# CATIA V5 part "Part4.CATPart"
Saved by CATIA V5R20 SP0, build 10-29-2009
Part number: Part4
Bounding box of the stored display mesh (mm): x -50 to 50, y -35 to 35, z 0 to 75
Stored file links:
  C:\Users\Lenovo\Desktop\存钱\Part4.CATPart
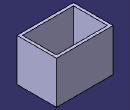
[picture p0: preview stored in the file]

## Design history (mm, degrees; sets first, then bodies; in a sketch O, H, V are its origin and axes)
Body1 (main body)
  Sketch1 on xy-plane, origin (0, 0, 0), H (1, 0, 0), V (0, 1, 0)
    line L1 (50, 35) -> (50, -35)
    line L2 (50, -35) -> (-50, -35)
    line L3 (-50, -35) -> (-50, 35)
    line L4 (-50, 35) -> (50, 35)
    length L4 = 100
    length L1 = 70
    vertical: L1 V, L3 V
    horizontal: L2 H, L4 H
    equidistance: L1 L3 O, L2 L4 O
  Pad1: profile Sketch1, direction (0, 0, 1), length 5
  Sketch2 on end face of Pad1, origin (0, 0, 5), H (1, 0, 0), V (0, 1, 0)
    line L1 (-50, 35) -> (-45, 35)
    line L2 (-45, 35) -> (-45, -35)
    line L3 (-45, -35) -> (-50, -35)
    line L4 (-50, -35) -> (-50, 35)
    reference projected line E1 (50, 35) -> (-50, 35) from edge [face of Pad1 from Sketch1.L4 | end face of Pad1]
    reference projected line E2 (-50, -35) -> (50, -35) from edge [face of Pad1 from Sketch1.L2 | end face of Pad1]
    reference projected line E3 (-50, 35) -> (-50, -35) from edge [face of Pad1 from Sketch1.L3 | end face of Pad1]
    length L1 = 5
    horizontal: L1 H, L3 H
    vertical: L2 V, L4 V
    coincidence: L1 E1, L3 E2, L4 E3
  Pad2: profile Sketch2, direction (0, 0, 1), length 70
  Mirror1: of the body so far, about yz-plane
  Sketch3 on face of Pad2, origin (0, -35, 0), H (1, 0, 0), V (0, 0, 1)
    line L1 (-50, 75) -> (50, 75)
    line L2 (50, 75) -> (50, 0)
    line L3 (50, 0) -> (-50, 0)
    line L4 (-50, 0) -> (-50, 75)
    reference projected line E1 (-50, 0) -> (50, 0) from edge [face of Mirror1 | face of Pad2]
    reference projected line E2 (50, 0) -> (50, 75) from edge [face of Mirror1 | face of Pad2]
    reference projected line E3 (-50, 0) -> (-50, 5) from edge [face of Pad2 | face of Pad2]
    reference projected line E4 (50, 75) -> (45, 75) from edge [face of Mirror1 | face of Pad2]
    horizontal: L1 H, L3 H
    vertical: L2 V, L4 V
    coincidence: L3 E1, L2 E2, L4 E3, L1 E4
  Pad3: profile Sketch3, direction (0, 1, 0), length 5
  Mirror2: of the body so far, about zx-plane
